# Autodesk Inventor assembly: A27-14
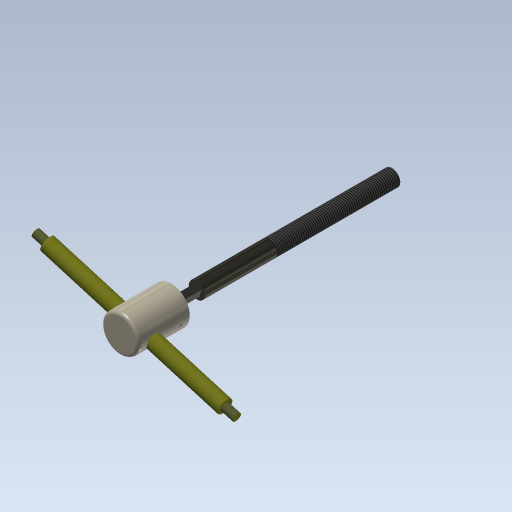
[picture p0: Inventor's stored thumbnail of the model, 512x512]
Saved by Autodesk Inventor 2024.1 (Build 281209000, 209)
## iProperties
Created: 2008-07
Part Number: A27-14
Document SubType Name: Assembly
Designer: y-shimohigashi
Stock Number: A24-14
Author: y-shimohigashi
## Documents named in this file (4)
- C:\Users\h-sato\Desktop\ブログ用モデル\Inventor\図面の作成\A27-14.iam
- C:\Users\h-sato\Desktop\R2024\Inventor2024基礎コース\練習問題\練習問題-27\P27-5締付ネジ.ipt
- C:\Users\h-sato\Desktop\R2024\Inventor2024基礎コース\練習問題\練習問題-27\P27-7ハンドル取付棒.ipt
- C:\Users\h-sato\Desktop\R2024\Inventor2024基礎コース\練習問題\練習問題-27\A27-8ハンドル部.iam
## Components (3 placed, 3 different names)
1. P27-5締付ネジ:1 — 角度:1
2. P27-7ハンドル取付棒:1 — メイト:1, 角度:1, メイト:2, メイト:3
3. A27-8ハンドル部:1 [sub-assembly] — メイト:1, メイト:2, メイト:3
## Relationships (4: Mate 3, Angle 1)
- メイト:1 [Mate]: P27-7ハンドル取付棒:1 ↔ A27-8ハンドル部:1
- 角度:1 [Angle]: P27-5締付ネジ:1 ↔ P27-7ハンドル取付棒:1
- メイト:2 [Mate]: P27-7ハンドル取付棒:1 ↔ A27-8ハンドル部:1
- メイト:3 [Mate]: P27-7ハンドル取付棒:1 ↔ A27-8ハンドル部:1
